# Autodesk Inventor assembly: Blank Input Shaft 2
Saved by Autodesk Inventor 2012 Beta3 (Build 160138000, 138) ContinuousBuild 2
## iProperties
Created: 2011-01
Part Number: Blank Input Shaft 2
Document SubType Name: Assembly
Designer: Beta-8540w
ClientObjectVersion: 1
Author: Beta-8540w
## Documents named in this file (2)
- C:\Inventor 2012 Essentials\Assemblies\Chapter 8\Design Accelerators\Blank Input Shaft 2.iam
- C:\Inventor 2012 Essentials\Assemblies\Chapter 8\Design Accelerators\Blank Input Shaft 2.ipt
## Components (1 placed, 1 different names)
1. Blank Input Shaft 2:1
